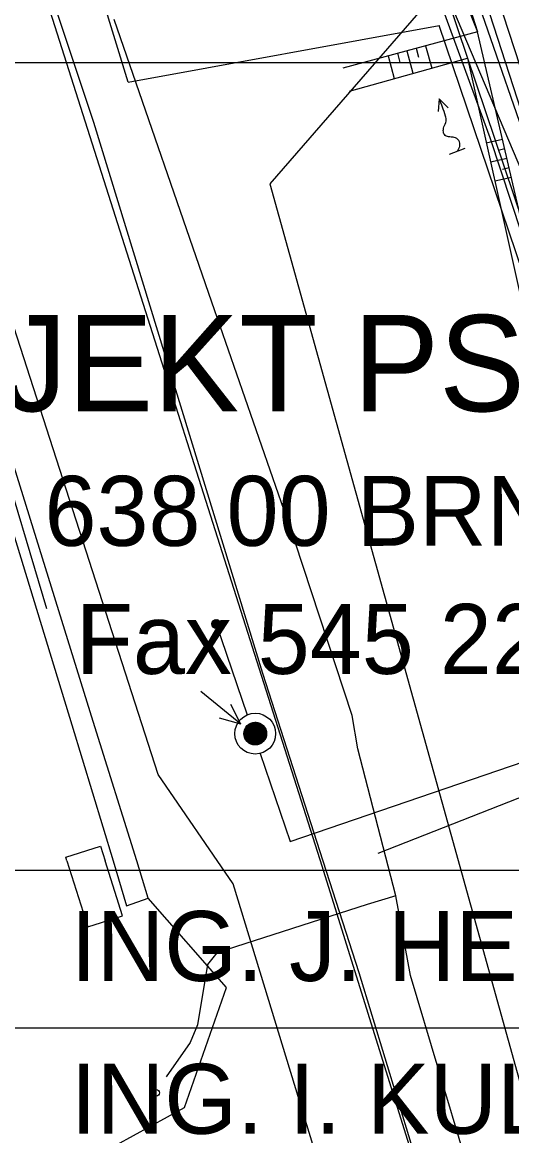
# Model space of a CAD drawing. Extents: x -439827 to -439102, y -1131353 to -1129707.
# Drawn here: x -439379 to -439341.3, y -1130721.2 to -1130635.3 of the extents above; entities that cross this region are included whole.
import ezdxf

# ---------------------------------------------------------------- set-up
doc = ezdxf.new("R2010")
doc.units = 0
for name, color, linetype in [('Vrstva 1', 7, 'Continuous'), ('Vrstva 10', 7, 'Continuous'), ('Vrstva 11', 7, 'Continuous'), ('Vrstva 16', 7, 'Continuous'), ('Vrstva 23', 7, 'Continuous'), ('Vrstva 34', 7, 'Continuous'), ('Vrstva 36', 7, 'Continuous'), ('Vrstva 48', 7, 'Continuous'), ('Vrstva 5', 7, 'Continuous'), ('Vrstva 52', 7, 'Continuous'), ('Vrstva 57', 7, 'Continuous'), ('Vrstva 59', 7, 'Continuous'), ('Vrstva 6', 7, 'Continuous'), ('Vrstva 61', 7, 'Continuous'), ('Vrstva 62', 7, 'Continuous'), ('Vrstva 63', 7, 'Continuous'), ('Vrstva 8', 7, 'Continuous'), ('Vrstva 9', 7, 'Continuous')]:
    doc.layers.add(name, color=color, linetype=linetype)

# ---------------------------------------------------------------- blocks, each defined once
blk = doc.blocks.new('KOTV_T')
at = {"layer": 'Vrstva 1'}
for p, q in [((-3.44, -0.33), (0.33, 3.44)), ((-3.42, 0.47), (-0.47, 3.42)), ((-3.31, -0.98), (0.98, 3.31)), ((-3.09, -1.54), (1.54, 3.09)), ((-3.06, 1.61), (-1.61, 3.06)), ((-2.8, -2.02), (2.02, 2.8)), ((-2.44, -2.44), (2.44, 2.44)), ((-2.02, -2.8), (2.8, 2.02)), ((-1.54, -3.09), (3.09, 1.54)), ((-0.98, -3.31), (3.31, 0.98)), ((-0.33, -3.44), (3.44, 0.33)), ((0.47, -3.42), (3.42, -0.47)), ((1.61, -3.06), (3.06, -1.61))]:
    blk.add_line(p, q, dxfattribs=at)
blk.add_circle((0, 0), 3.45, dxfattribs=at)
blk = doc.blocks.new('POL_SI')
at = {"layer": 'Vrstva 1'}
for q in [(25.71, 30.64), (4.84, 16.31), (15.23, 7.59)]:
    blk.add_line((0, 0), q, dxfattribs=at)

msp = doc.modelspace()

# ---------------------------------------------------------------- linework, layer by layer
at = {"layer": 'Vrstva 10'}
for p, q in [((-439350.074, -1130637.696), (-439349.886, -1130638.396)), ((-439349.35, -1130637.5), (-439348.878, -1130639.24)), ((-439348.624, -1130637.306), (-439348.438, -1130638)), ((-439347.902, -1130637.11), (-439347.434, -1130638.836)), ((-439350.798, -1130637.892), (-439350.324, -1130639.642)), ((-439341.958, -1130644.348), (-439343.216, -1130644.638)), ((-439341.788, -1130645.078), (-439342.294, -1130645.196)), ((-439341.62, -1130645.81), (-439342.888, -1130646.102)), ((-439341.45, -1130646.538), (-439341.96, -1130646.658)), ((-439341.28, -1130647.27), (-439342.562, -1130647.568))]:
    msp.add_line(p, q, dxfattribs=at)
at = {"layer": 'Vrstva 11'}
for points in [[(-439377.206, -1130631.936), (-439373.528, -1130643.02), (-439360.492, -1130685.522), (-439355.836, -1130700)], [(-439370.202, -1130700), (-439373.55, -1130689.254), (-439387.262, -1130645.142), (-439388.614, -1130643.778), (-439389.866, -1130643.474), (-439393.512, -1130644.264), (-439394.208, -1130644.94), (-439394.564, -1130645.832), (-439390.252, -1130644.828), (-439389.416, -1130644.948), (-439388.656, -1130645.546), (-439375.202, -1130689.506), (-439372.026, -1130700)], [(-439372.026, -1130700), (-439370.976, -1130703.472), (-439369.302, -1130702.892)], [(-439363.274, -1130709.776), (-439369.302, -1130702.892), (-439370.202, -1130700)], [(-439355.836, -1130700), (-439353.066, -1130708.616), (-439349.052, -1130721.796), (-439345.164, -1130734.324), (-439339.204, -1130753.614), (-439333.67, -1130771.382), (-439327.41, -1130792.132), (-439322.676, -1130807.066)], [(-439409.932, -1130743.142), (-439403.332, -1130739.482), (-439394.1, -1130734.16), (-439366.514, -1130719.04), (-439363.274, -1130709.776)]]:
    msp.add_lwpolyline(points, dxfattribs=at)
at = {"layer": 'Vrstva 16'}
msp.add_line((-439387.604, -1130645.578), (-439377.158, -1130680.546), dxfattribs=at)
at = {"layer": 'Vrstva 23'}
for points in [[(-439375.58, -1130700), (-439375.664, -1130699.734), (-439372.982, -1130698.886), (-439372.63, -1130700)], [(-439375.58, -1130700), (-439373.968, -1130705.096), (-439371.286, -1130704.248), (-439372.63, -1130700)]]:
    msp.add_lwpolyline(points, dxfattribs=at)
at = {"layer": 'Vrstva 34'}
for p, q in [((-439355.89, -1130700.43), (-439386.61, -1130603.79)), ((-439368.55, -1130693.36), (-439384.6, -1130643.6)), ((-439362.76, -1130701.78), (-439368.55, -1130693.36)), ((-439318.14, -1130821.18), (-439355.89, -1130700.43)), ((-439297.84, -1130914.25), (-439362.76, -1130701.78))]:
    msp.add_line(p, q, dxfattribs=at)
at = {"layer": 'Vrstva 36'}
for p, q in [((-439370.86, -1130639.92), (-439374.92, -1130626.65)), ((-439370.86, -1130639.92), (-439346.85, -1130635.55)), ((-439323.66, -1130704.2), (-439346.85, -1130635.55))]:
    msp.add_line(p, q, dxfattribs=at)
msp.add_circle((-439368.693, -1130717.91), 0.25, dxfattribs=at)
at = {"layer": 'Vrstva 48'}
for p, q in [((-439346.855, -1130641.196), (-439346.94, -1130642.182)), ((-439346.855, -1130641.196), (-439346.156, -1130641.893)), ((-439344.873, -1130645.052), (-439346.096, -1130645.498))]:
    msp.add_line(p, q, dxfattribs=at)
msp.add_spline([(-439345.486, -1130645.28), (-439345.272, -1130644.877), (-439345.35, -1130644.422), (-439345.7, -1130644.194), (-439346.02, -1130644.15), (-439346.399, -1130644.028), (-439346.53, -1130643.754), (-439346.486, -1130643.381), (-439346.31, -1130642.934), (-439346.369, -1130642.535), (-439346.855, -1130641.196)], degree=3, dxfattribs=at)
at = {"layer": 'Vrstva 5'}
msp.add_lwpolyline([(-439277.797, -1130823.31), (-439296.36, -1130772.17), (-439314.646, -1130718.277), (-439334.211, -1130661.631), (-439352.883, -1130603.988)], dxfattribs=at)
at = {"layer": 'Vrstva 52'}
for p, q in [((-439364.39, -1130656.89), (-439371.93, -1130635.09)), ((-439357.96, -1130675.41), (-439364.39, -1130656.89)), ((-439353.58, -1130688.8), (-439357.96, -1130675.41)), ((-439353.14, -1130691.38), (-439353.58, -1130688.8)), ((-439350.2, -1130702.7), (-439353.14, -1130691.38)), ((-439350.2, -1130702.7), (-439352.4, -1130703.38)), ((-439349.06, -1130708.87), (-439350.2, -1130702.7)), ((-439352.4, -1130703.38), (-439364.01, -1130707.1)), ((-439364.01, -1130707.1), (-439364.73, -1130708.01)), ((-439364.73, -1130708.01), (-439365.52, -1130712.66)), ((-439342.32, -1130731.46), (-439349.06, -1130708.87)), ((-439365.52, -1130712.66), (-439366.07, -1130714.02)), ((-439366.07, -1130714.02), (-439367.931, -1130716.685))]:
    msp.add_line(p, q, dxfattribs=at)
at = {"layer": 'Vrstva 57'}
for p, q in [((-439346.839, -1130632.703), (-439359.919, -1130647.77)), ((-439359.919, -1130647.77), (-439317.435, -1130800.508)), ((-439364.063, -1130681.732), (-439361.679, -1130688.749)), ((-439358.354, -1130698.532), (-439324.871, -1130687.057)), ((-439361.007, -1130691.07), (-439361.925, -1130690.172)), ((-439360.985, -1130691.069), (-439361.924, -1130690.149)), ((-439360.963, -1130691.067), (-439361.923, -1130690.127)), ((-439360.941, -1130691.064), (-439361.921, -1130690.106)), ((-439360.92, -1130691.062), (-439361.918, -1130690.085)), ((-439360.9, -1130691.058), (-439361.915, -1130690.065)), ((-439360.88, -1130691.055), (-439361.912, -1130690.044)), ((-439360.86, -1130691.05), (-439361.908, -1130690.025)), ((-439360.841, -1130691.046), (-439361.904, -1130690.005)), ((-439360.822, -1130691.041), (-439361.9, -1130689.986)), ((-439360.804, -1130691.036), (-439361.895, -1130689.968)), ((-439360.786, -1130691.03), (-439361.89, -1130689.95)), ((-439360.768, -1130691.024), (-439361.884, -1130689.932)), ((-439360.75, -1130691.018), (-439361.879, -1130689.914)), ((-439360.733, -1130691.012), (-439361.873, -1130689.897)), ((-439360.716, -1130691.005), (-439361.866, -1130689.88)), ((-439360.7, -1130690.998), (-439361.859, -1130689.863)), ((-439360.683, -1130690.99), (-439361.852, -1130689.846)), ((-439360.667, -1130690.983), (-439361.845, -1130689.83)), ((-439360.651, -1130690.975), (-439361.838, -1130689.814)), ((-439360.636, -1130690.967), (-439361.83, -1130689.799)), ((-439360.621, -1130690.958), (-439361.822, -1130689.783)), ((-439360.606, -1130690.95), (-439361.813, -1130689.768)), ((-439360.591, -1130690.941), (-439361.805, -1130689.753)), ((-439360.576, -1130690.932), (-439361.796, -1130689.738)), ((-439360.562, -1130690.922), (-439361.787, -1130689.724)), ((-439360.548, -1130690.913), (-439361.778, -1130689.71)), ((-439360.534, -1130690.903), (-439361.768, -1130689.696)), ((-439360.521, -1130690.893), (-439361.758, -1130689.682)), ((-439360.508, -1130690.883), (-439361.748, -1130689.668)), ((-439360.495, -1130690.872), (-439361.738, -1130689.655)), ((-439360.482, -1130690.861), (-439361.728, -1130689.642)), ((-439360.469, -1130690.85), (-439361.717, -1130689.629)), ((-439360.457, -1130690.839), (-439361.706, -1130689.617)), ((-439360.445, -1130690.828), (-439361.695, -1130689.604)), ((-439360.433, -1130690.816), (-439361.683, -1130689.592)), ((-439360.421, -1130690.804), (-439361.672, -1130689.58)), ((-439360.409, -1130690.792), (-439361.66, -1130689.568)), ((-439360.398, -1130690.78), (-439361.648, -1130689.557)), ((-439360.387, -1130690.767), (-439361.635, -1130689.546)), ((-439360.376, -1130690.754), (-439361.623, -1130689.535)), ((-439360.366, -1130690.741), (-439361.61, -1130689.524)), ((-439360.356, -1130690.728), (-439361.597, -1130689.513)), ((-439360.346, -1130690.715), (-439361.584, -1130689.503)), ((-439360.336, -1130690.701), (-439361.571, -1130689.493)), ((-439360.326, -1130690.687), (-439361.557, -1130689.483)), ((-439360.317, -1130690.673), (-439361.543, -1130689.473)), ((-439360.308, -1130690.659), (-439361.529, -1130689.464)), ((-439360.299, -1130690.644), (-439361.514, -1130689.454)), ((-439360.29, -1130690.629), (-439361.5, -1130689.445)), ((-439360.282, -1130690.614), (-439361.485, -1130689.437)), ((-439360.273, -1130690.599), (-439361.47, -1130689.428)), ((-439360.266, -1130690.583), (-439361.454, -1130689.42)), ((-439360.258, -1130690.567), (-439361.438, -1130689.412)), ((-439360.251, -1130690.551), (-439361.422, -1130689.404)), ((-439360.243, -1130690.535), (-439361.406, -1130689.397)), ((-439360.237, -1130690.518), (-439361.39, -1130689.39)), ((-439360.23, -1130690.501), (-439361.373, -1130689.383)), ((-439360.224, -1130690.484), (-439361.356, -1130689.376)), ((-439360.218, -1130690.466), (-439361.338, -1130689.37)), ((-439360.213, -1130690.448), (-439361.321, -1130689.364)), ((-439360.207, -1130690.43), (-439361.303, -1130689.358)), ((-439360.202, -1130690.412), (-439361.284, -1130689.353)), ((-439360.198, -1130690.393), (-439361.265, -1130689.348)), ((-439360.194, -1130690.374), (-439361.246, -1130689.343)), ((-439360.19, -1130690.354), (-439361.227, -1130689.339)), ((-439360.186, -1130690.334), (-439361.207, -1130689.335)), ((-439360.183, -1130690.314), (-439361.187, -1130689.332)), ((-439360.181, -1130690.293), (-439361.166, -1130689.329)), ((-439360.179, -1130690.271), (-439361.145, -1130689.326)), ((-439360.177, -1130690.25), (-439361.123, -1130689.324)), ((-439360.176, -1130690.227), (-439361.101, -1130689.323)), ((-439360.175, -1130690.205), (-439361.078, -1130689.322)), ((-439360.176, -1130690.181), (-439361.054, -1130689.321)), ((-439360.176, -1130690.157), (-439361.03, -1130689.322)), ((-439360.178, -1130690.132), (-439361.006, -1130689.322)), ((-439360.18, -1130690.107), (-439360.98, -1130689.324)), ((-439360.183, -1130690.081), (-439360.954, -1130689.327)), ((-439360.187, -1130690.053), (-439360.926, -1130689.33)), ((-439360.192, -1130690.025), (-439360.898, -1130689.335)), ((-439360.199, -1130689.995), (-439360.868, -1130689.341)), ((-439360.207, -1130689.964), (-439360.837, -1130689.348)), ((-439360.217, -1130689.931), (-439360.804, -1130689.357)), ((-439360.228, -1130689.896), (-439360.768, -1130689.368)), ((-439360.243, -1130689.858), (-439360.73, -1130689.382)), ((-439360.262, -1130689.817), (-439360.688, -1130689.4)), ((-439360.287, -1130689.769), (-439360.64, -1130689.423)), ((-439360.322, -1130689.711), (-439360.581, -1130689.458)), ((-439360.394, -1130689.617), (-439360.486, -1130689.528)), ((-439361.03, -1130691.071), (-439361.925, -1130690.195)), ((-439361.054, -1130691.071), (-439361.925, -1130690.218)), ((-439361.078, -1130691.071), (-439361.924, -1130690.243)), ((-439361.103, -1130691.07), (-439361.923, -1130690.268)), ((-439361.129, -1130691.068), (-439361.92, -1130690.293)), ((-439361.155, -1130691.065), (-439361.917, -1130690.32)), ((-439361.183, -1130691.061), (-439361.912, -1130690.348)), ((-439361.212, -1130691.056), (-439361.907, -1130690.376)), ((-439361.242, -1130691.05), (-439361.9, -1130690.406)), ((-439361.274, -1130691.042), (-439361.891, -1130690.438)), ((-439361.307, -1130691.033), (-439361.881, -1130690.471)), ((-439361.343, -1130691.021), (-439361.868, -1130690.507)), ((-439361.383, -1130691.006), (-439361.853, -1130690.546)), ((-439361.426, -1130690.987), (-439361.832, -1130690.589)), ((-439361.477, -1130690.961), (-439361.805, -1130690.639)), ((-439361.541, -1130690.921), (-439361.764, -1130690.702)), ((-439360.668, -1130691.721), (-439358.354, -1130698.532))]:
    msp.add_line(p, q, dxfattribs=at)
for radius in [1.575, 0.875]:
    msp.add_circle((-439361.05, -1130690.196), radius, dxfattribs=at)
at = {"layer": 'Vrstva 59'}
msp.add_line((-439322.958, -1130688.178), (-439346.578, -1130632.414), dxfattribs=at)
msp.add_lwpolyline([(-439240.615, -1130935.08), (-439245.006, -1130936.575), (-439254.477, -1130905.195), (-439274.831, -1130847.058), (-439298.026, -1130780.807), (-439307.773, -1130752.965), (-439314.372, -1130732.153), (-439325.758, -1130696.243), (-439342.929, -1130644.213), (-439353.367, -1130615.721)], dxfattribs=at)
at = {"layer": 'Vrstva 6'}
msp.add_line((-439351.56, -1130699.424), (-439322.958, -1130688.178), dxfattribs=at)
at = {"layer": 'Vrstva 61'}
msp.add_line((-439352.156, -1130603.174), (-439333.292, -1130661.29), dxfattribs=at)
at = {"layer": 'Vrstva 62'}
msp.add_line((-439334.327, -1130661.321), (-439354.141, -1130603.913), dxfattribs=at)
at = {"layer": 'Vrstva 63'}
msp.add_lwpolyline([(-439279.55, -1130829.627), (-439292.524, -1130791.32), (-439307.367, -1130752.78), (-439315.541, -1130727.251), (-439322.482, -1130704.449), (-439333.14, -1130672.167), (-439347.586, -1130629.381), (-439352.159, -1130615.872), (-439360.579, -1130591.518), (-439378.343, -1130536.883)], dxfattribs=at)
at = {"layer": 'Vrstva 8'}
for p, q in [((-439688.772, -1130638.427), (-439314.563, -1130638.406)), ((-439688.76, -1130700.735), (-439314.538, -1130700.729)), ((-439688.772, -1130712.892), (-439314.565, -1130712.9))]:
    msp.add_line(p, q, dxfattribs=at)
at = {"layer": 'Vrstva 9'}
for points in [[(-439351.164, -1130621.958), (-439349.2, -1130622.824), (-439343.888, -1130636.026)], [(-439351.164, -1130621.958), (-439348.35, -1130622.064), (-439343.888, -1130636.026)], [(-439329.016, -1130691.134), (-439339.192, -1130656.276), (-439343.888, -1130636.026), (-439354.284, -1130638.834)], [(-439353.788, -1130640.606), (-439344.68, -1130638.07), (-439340.524, -1130656.706), (-439329.016, -1130691.134)]]:
    msp.add_lwpolyline(points, dxfattribs=at)

# ---------------------------------------------------------------- block references
at = {"layer": 'Vrstva 57', "xscale": 0.10000000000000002, "yscale": 0.1}
for name, p, rotation in [('KOTV_T', (-439364.063, -1130681.732), 1), ('POL_SI', (-439362.166, -1130689.473), 90.62154920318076)]:
    msp.add_blockref(name, p, dxfattribs=dict(at, rotation=rotation))

# ---------------------------------------------------------------- texts
at = {"layer": 'Vrstva 8'}
for s, height, p in [('AGROPROJEKT PSO  s.r.o.', 7.42447, (-439431.267, -1130665.318)), ('Slavíčkova 1b, 638 00 BRNO', 5.39947, (-439426.283, -1130675.704)), ('Tel. 54522 22 58   Fax 545 22 22 61', 5.39992, (-439435.12, -1130685.586)), ('ING. J. HERMANY', 5.39992, (-439375.289, -1130709.285)), ('ING. I. KULÍSEK', 5.39999, (-439375.287, -1130721.075))]:
    msp.add_text(s, height=height, rotation=0.00063, dxfattribs=at).set_placement(p)

doc.saveas('drawing.dxf')
